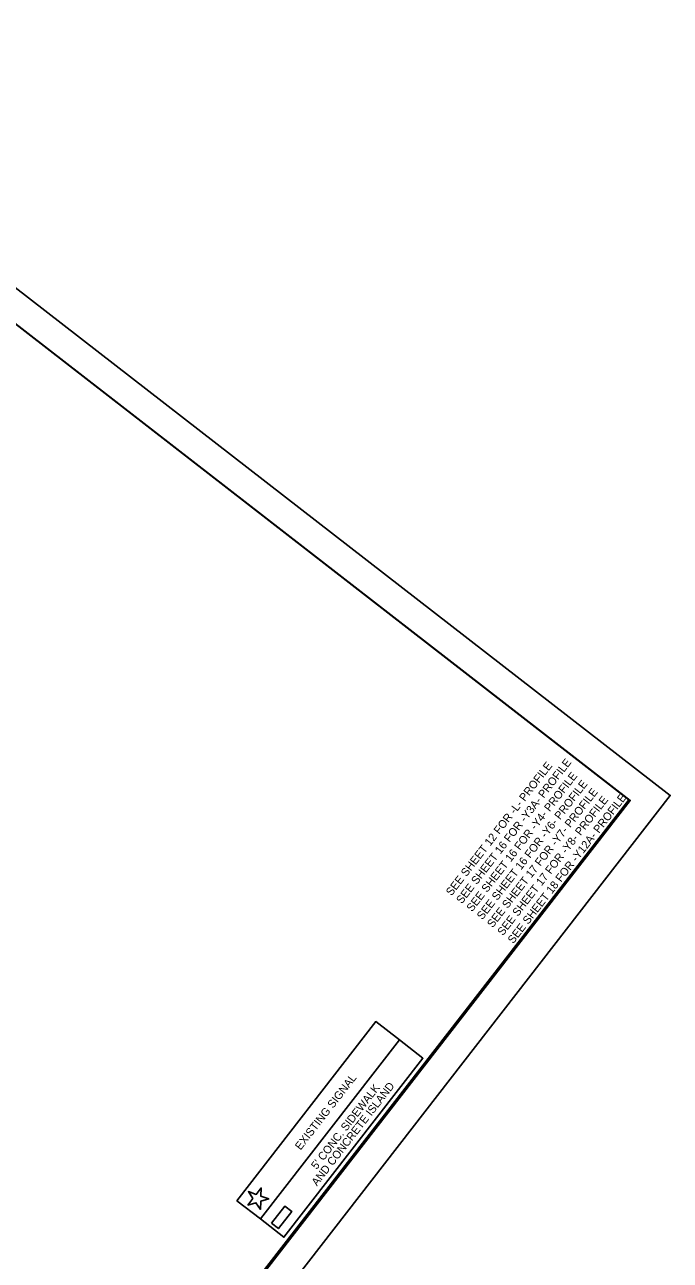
# Model space of a CAD drawing. Extents: x 2013373 to 2015284, y 444618 to 446636.
# Drawn here: x 2014719 to 2015284, y 445555 to 446636 of the extents above; entities that cross this region are included whole.
import ezdxf

# ---------------------------------------------------------------- set-up
doc = ezdxf.new("R2010")
doc.units = 0
for name, color, linetype in [('Old_Level_2', 7, 'Continuous'), ('Prop Conc 4in Sidewalk', 7, 'Continuous'), ('Prop Conc 5in Monolithic Keyed In Island', 7, 'Continuous'), ('Prop Horizontal Alignment', 7, 'Continuous'), ('Prop Horizontal Alignment Station Label', 7, 'Continuous'), ('Prop Lane Arrow CELL', 7, 'Continuous'), ('Prop Noise Wall', 7, 'Continuous')]:
    doc.layers.add(name, color=color, linetype=linetype)

msp = doc.modelspace()

# ---------------------------------------------------------------- linework, layer by layer
at = {"layer": 'Old_Level_2'}
for points in [[(2014904.7, 445606.9), (2015026.2, 445763.5), (2015046.8, 445747.5), (2014925.3, 445590.9)], [(2014925.3, 445590.9), (2015046.8, 445747.5), (2015067.4, 445731.5), (2014945.9, 445574.9)]]:
    msp.add_lwpolyline(points, close=True, dxfattribs=at)
at = {"layer": 'Prop Conc 4in Sidewalk'}
msp.add_lwpolyline([(2014935, 445587.1), (2014946.7, 445602.2), (2014952.7, 445597.5), (2014941, 445582.5)], close=True, dxfattribs=at)
at = {"layer": 'Prop Conc 5in Monolithic Keyed In Island'}
msp.add_lwpolyline([(2014241.9, 444618), (2015283.7, 445961.4), (2014414.5, 446635.5), (2013372.7, 445292.2)], close=True, dxfattribs=at)
at = {"layer": 'Prop Horizontal Alignment'}
msp.add_lwpolyline([(2014418.9, 446600.4), (2013499.7, 445415.1), (2014329.4, 444771.6), (2015248.7, 445957)], close=True, dxfattribs=at)
at = {"layer": 'Prop Lane Arrow CELL'}
msp.add_lwpolyline([(2014918.8, 445608.8), (2014914.4, 445603.1), (2014921.3, 445605.1), (2014925.4, 445599.2), (2014925.6, 445606.4), (2014932.6, 445608.4), (2014925.8, 445610.8), (2014926, 445618), (2014921.6, 445612.3), (2014914.8, 445614.8), (2014918.8, 445608.8)], dxfattribs=at)
at = {"layer": 'Prop Noise Wall'}
msp.add_lwpolyline([(2014144.5, 446243.4), (2013513.1, 445427.6), (2013603.8, 445375.4), (2013612.4, 445329.9), (2013915.8, 445258.4), (2014042, 445083.4), (2014361.1, 444814.9), (2015247.4, 445957.6), (2014564.2, 446487.5), (2014441.6, 446328.9), (2014350.5, 446399.7), (2014197.2, 446202.4)], close=True, dxfattribs=at)

# ---------------------------------------------------------------- texts
at = {"layer": 'Prop Horizontal Alignment Station Label'}
for s, p in [('SEE SHEET 12 FOR -L- PROFILE', (2015092.4, 445873)), ('SEE SHEET 16 FOR -Y3A- PROFILE', (2015101.4, 445866)), ('SEE SHEET 16 FOR -Y4- PROFILE', (2015110.4, 445859.1)), ('SEE SHEET 16 FOR -Y6- PROFILE', (2015119.4, 445852.1)), ('SEE SHEET 17 FOR -Y7- PROFILE', (2015128.4, 445845.1)), ('SEE SHEET 17 FOR -Y8- PROFILE', (2015137.4, 445838.2)), ('SEE SHEET 18 FOR -Y12A- PROFILE', (2015146.4, 445831.2)), ('EXISTING SIGNAL', (2014960.4, 445650.6)), ("5' CONC. SIDEWALK", (2014974.5, 445633.7)), ('AND CONCRETE ISLAND', (2014974.8, 445619.2))]:
    msp.add_text(s, height=7, rotation=52.2051, dxfattribs=at).set_placement(p)

doc.saveas('drawing.dxf')
